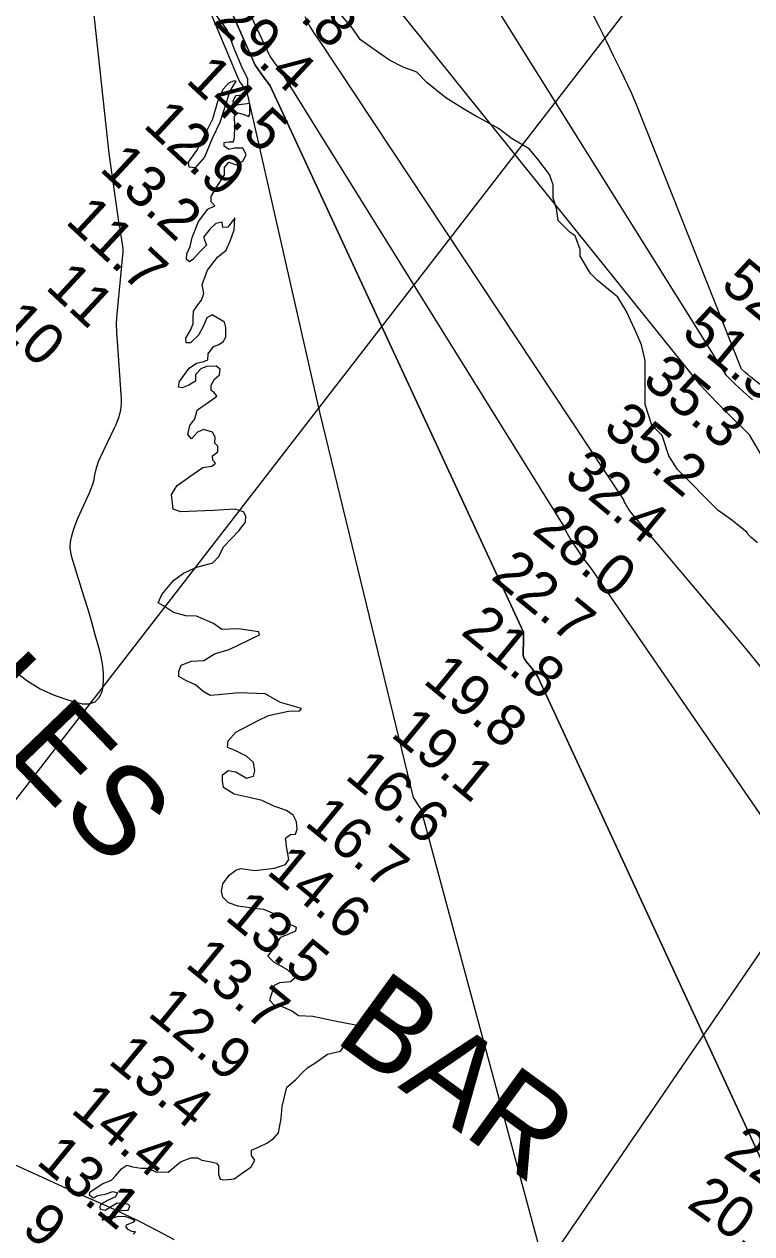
# Model space of a CAD drawing. Extents: x 3161615 to 3199515, y 867541 to 892976.
# Drawn here: x 3182551 to 3183730, y 879343 to 881302 of the extents above; entities that cross this region are included whole.
import ezdxf

# ---------------------------------------------------------------- set-up
doc = ezdxf.new("R2010")
doc.units = 0
for name, color, linetype in [('V-RIVR-EDGE', 7, 'Continuous'), ('V-RIVR-IDEN', 7, 'Continuous'), ('V-RIVR-RANG', 7, 'Continuous'), ('V-SITE-VEGE', 7, 'Continuous'), ('V-TOPO-DPTH', 7, 'Continuous'), ('V-TOPO-MAJR', 7, 'Continuous'), ('V-TOPO-MINR', 7, 'Continuous'), ('V-TOPO-WATR', 7, 'Continuous')]:
    doc.layers.add(name, color=color, linetype=linetype)

msp = doc.modelspace()

# ---------------------------------------------------------------- linework, layer by layer
at = {"layer": 'V-RIVR-EDGE'}
for points in [[(3182813, 880793.6), (3182820.6, 880806.9), (3182824.5, 880816.9), (3182824.5, 880826), (3182825, 880837.4), (3182830.7, 880845.5), (3182838.4, 880855.5), (3182841.8, 880866), (3182839.4, 880880.8), (3182848.1, 880903.6), (3182864.3, 880925), (3182878.2, 880936.5), (3182885.4, 880952.2), (3182891.1, 880968.9), (3182892.1, 880988.4), (3182880.7, 880973.6), (3182873, 880973.2), (3182871.6, 880981.8), (3182861.6, 880979.4), (3182852, 880970.9), (3182841.5, 880957.1), (3182846.3, 880944.2), (3182835.7, 880933.7), (3182824.3, 880921.3), (3182818.5, 880917.1), (3182813.8, 880920.9), (3182814.3, 880930.4), (3182820, 880942.3), (3182822.9, 880956.6), (3182833.5, 880982.8), (3182848.3, 881002.8), (3182859.8, 881008), (3182853.6, 881014.7), (3182854.1, 881023.3), (3182863.2, 881039), (3182875.6, 881058.5), (3182875.7, 881070), (3182882.3, 881078.6), (3182894.3, 881074.7), (3182905.7, 881080.9), (3182910.5, 881091.4), (3182905.3, 881101.4), (3182891.9, 881101.4), (3182882.4, 881099.1), (3182874.8, 881104.8), (3182874.8, 881110.5), (3182882.4, 881111.5), (3182890.1, 881111.9), (3182891.5, 881118.6), (3182892, 881136.7), (3182891.6, 881153.4), (3182897.8, 881158.6), (3182905, 881156.7), (3182915, 881152.9), (3182916.4, 881157.6), (3182916.4, 881173.8), (3182899.3, 881171.5), (3182891.2, 881170.1), (3182889.3, 881177.7), (3182893.6, 881186.8), (3182905, 881187.7), (3182910.3, 881193.4), (3182913.2, 881203.4), (3182913.2, 881213.4), (3182903.2, 881234), (3182891.4, 881263.1), (3182880, 881293.2), (3182862.4, 881316.1)], [(3182893.6, 881209.7), (3182887.9, 881200.1), (3182883.6, 881192.5), (3182878.8, 881176.3), (3182867.7, 881143), (3182855.7, 881117.3), (3182843.3, 881086.8), (3182828, 881069.6), (3182818, 881070.6), (3182817, 881078.7), (3182830.4, 881097.8), (3182846.2, 881128.2), (3182856.3, 881148.7), (3182864.9, 881176.8), (3182873.1, 881196.8)], [(3182873.1, 881196.8), (3182882.7, 881207.3), (3182891.7, 881211.1), (3182893.6, 881209.7)], [(3182928.8, 880173.8), (3182946.9, 880182.3), (3182979.3, 880189.4), (3182997.5, 880190.3), (3183000.3, 880193.7), (3182966, 880203.8), (3182941.3, 880217.7), (3182898.8, 880219.2), (3182865.9, 880215.9), (3182852.1, 880215), (3182840.2, 880222.2), (3182828.3, 880232.2), (3182812.6, 880239.4), (3182801.6, 880245.7), (3182801.6, 880253.8), (3182805, 880264.2), (3182822.2, 880270.4), (3182842.2, 880271.8), (3182859.4, 880282.2), (3182883.3, 880289.3), (3182932, 880313.1), (3182931, 880318.3), (3182897.6, 880323.1), (3182871.4, 880321.8), (3182857.6, 880331.8), (3182830, 880343.3), (3182812.8, 880343.9), (3182792.8, 880349.6), (3182776.6, 880360.2), (3182768, 880365), (3182773.8, 880378.8), (3182792.9, 880401.1), (3182809.2, 880413), (3182830.7, 880423), (3182856.4, 880429.6), (3182866.5, 880440.1), (3182873.7, 880455.8), (3182898.5, 880481.9), (3182909.5, 880495.7), (3182910, 880505.3), (3182906.2, 880512.4), (3182892.4, 880516.8), (3182857.1, 880514.5), (3182804.6, 880512.2), (3182792.3, 880516.5), (3182789.5, 880540.4), (3182799, 880555.2), (3182819.1, 880569.9), (3182840.1, 880584.1), (3182854.9, 880586.5), (3182861.1, 880591.2), (3182856.4, 880596), (3182855.9, 880603.2), (3182864.5, 880609.4), (3182864.5, 880618.9), (3182859.8, 880623.7), (3182860.3, 880633.2), (3182856, 880641.3), (3182841.2, 880645.7), (3182831.7, 880641.4), (3182822.1, 880630.4), (3182815.9, 880637.6), (3182819.3, 880652.4), (3182827.4, 880663.3), (3182831.3, 880677.2), (3182839.4, 880682.9), (3182849, 880689.5), (3182862.8, 880699.5), (3182858.5, 880705.7), (3182853.8, 880709.1), (3182853.8, 880717.6), (3182859.1, 880727.2), (3182867.2, 880734.3), (3182868.2, 880743.3), (3182862, 880748.1), (3182846.2, 880747.7), (3182837.2, 880743.9), (3182828.6, 880734.4), (3182828.5, 880723.9), (3182817.6, 880717.7), (3182806.6, 880713.5), (3182800.9, 880714.4), (3182802.3, 880723.5), (3182818.1, 880744.9), (3182830, 880753), (3182842, 880755.8), (3182848.2, 880758.7), (3182849.2, 880768.2), (3182857.8, 880780.1), (3182865.4, 880782.9), (3182873.5, 880787.7), (3182877.4, 880795.3), (3182877.9, 880811), (3182875.5, 880819.6), (3182855.5, 880831.6), (3182846.9, 880826.9), (3182841.2, 880813.5), (3182833.5, 880798.3), (3182820.1, 880786.4), (3182813.4, 880786.4), (3182813, 880793.6)], [(3182750, 879449.6), (3182764.3, 879443.2), (3182784.4, 879443.1), (3182804.4, 879459.8), (3182821.1, 879466.4), (3182831.6, 879466.4), (3182838.8, 879462.5), (3182854, 879459.6), (3182862.6, 879457.7), (3182865.9, 879453.4), (3182865.9, 879439.6), (3182868.3, 879431.5), (3182874.5, 879430.5), (3182886.4, 879431.4), (3182891.2, 879432.4), (3182918.9, 879451.4), (3182924.6, 879462.3), (3182919.4, 879470), (3182919.4, 879478.5), (3182931.8, 879483.8), (3182945.2, 879490.4), (3182955.2, 879498), (3182962.9, 879506.6), (3182967.2, 879529.9), (3182968.7, 879549.5), (3182976.4, 879580.5), (3182990.7, 879592.3), (3183001.3, 879603.8), (3183010.3, 879612.3), (3183023.7, 879620.4), (3183042.3, 879634.2), (3183063.3, 879638.9), (3183076.7, 879657), (3183092.5, 879664.6), (3183098.7, 879677), (3183087.8, 879680.8), (3183051.5, 879688), (3183018.7, 879694.8), (3182995.3, 879696.3), (3182983.9, 879704), (3182967.7, 879711.1), (3182956.2, 879713.6), (3182949.1, 879720.7), (3182951, 879729.3), (3182956.3, 879746), (3182964.9, 879750.3), (3182982.6, 879751.6), (3182990.7, 879758.8), (3182977.4, 879770.7), (3182965, 879777.9), (3182955.4, 879783.2), (3182945.9, 879792.7), (3182956.5, 879807), (3182967, 879823.7), (3182981.3, 879829.4), (3182990.9, 879833.6), (3182992.3, 879839.4), (3182977.5, 879846.1), (3182970.4, 879856.1), (3182959.9, 879859.9), (3182939, 879868.1), (3182928.5, 879869.6), (3182897.5, 879873.9), (3182882.2, 879879.2), (3182872.7, 879888.3), (3182870.4, 879897.8), (3182872.8, 879909.8), (3182882.8, 879924), (3182893.8, 879932.1), (3182901.9, 879935), (3182924.8, 879931.6), (3182956.3, 879935.3), (3182974.4, 879941), (3182979.7, 879949.1), (3182976.4, 879967.2), (3182974.1, 879983.9), (3182982.7, 879989.6), (3182990.3, 879990.1), (3182993.2, 879998.2), (3182992.3, 880010.6), (3182986.6, 880021.1), (3182976.1, 880028.7), (3182955.6, 880035.5), (3182936.5, 880045), (3182915.6, 880049.9), (3182891.3, 880055.2), (3182874.1, 880066.2), (3182872.2, 880076.7), (3182872.3, 880086.7), (3182881.3, 880093.3), (3182893.7, 880091.4), (3182910.9, 880081.3), (3182922.3, 880084.2), (3182924.7, 880092.8), (3182922.4, 880106.6), (3182911.4, 880116.6), (3182893.8, 880125.3), (3182880.5, 880130.5), (3182881.5, 880141.5), (3182893.9, 880155.3), (3182928.8, 880173.8)], [(3182719.3, 879349.8), (3182715.9, 879353.9), (3182716.4, 879357.7), (3182727.4, 879362), (3182730.3, 879363.9), (3182726, 879367), (3182713.8, 879371), (3182700.7, 879370.6), (3182688.1, 879366.3), (3182677.1, 879365.2), (3182680, 879369), (3182691, 879372.1), (3182694.1, 879377.3), (3182695.5, 879380.2), (3182707.9, 879381.1), (3182719.1, 879381.5), (3182722.2, 879387.7), (3182718.7, 879391.3), (3182701.5, 879392.8), (3182690.5, 879386.4), (3182681.9, 879380.9), (3182674.5, 879382.3), (3182674.1, 879387.4), (3182675.7, 879391.9), (3182686.5, 879397.8), (3182699.4, 879403.7), (3182702, 879409.5), (3182693.7, 879410.9), (3182681.3, 879406.9), (3182669.6, 879404.5), (3182662.4, 879400.7), (3182656.7, 879405.5), (3182657.4, 879410.3), (3182677.3, 879423.8), (3182692.1, 879429.8), (3182699, 879437.1), (3182709, 879448.8), (3182717.1, 879454), (3182726.2, 879451.4), (3182740.5, 879449.4), (3182750, 879449.6)], [(3182727.8, 879342.6), (3182731.4, 879346.2), (3182725.5, 879346.7), (3182719.3, 879349.8)]]:
    msp.add_lwpolyline(points, dxfattribs=at)
at = {"layer": 'V-RIVR-RANG'}
for p, q in [((3181801.2, 879095.8), (3184051.7, 882002.4)), ((3182760.7, 878360.6), (3184853.5, 881422.8))]:
    msp.add_line(p, q, dxfattribs=at)
at = {"layer": 'V-SITE-VEGE'}
for points in [[(3183123.7, 881257.7), (3183096.1, 881277), (3183082.3, 881296.3), (3183038.1, 881348.8)], [(3183739.6, 880462), (3183728.9, 880471.1), (3183726, 880474), (3183724, 880476.4), (3183722.7, 880479), (3183695.1, 880501), (3183675.8, 880514.8), (3183609.6, 880581.1), (3183595.8, 880603.2), (3183584.7, 880636.3), (3183568.2, 880652.9), (3183557.1, 880686), (3183557.1, 880757.8), (3183551.6, 880782.7), (3183540.5, 880807.5), (3183526.7, 880837.9), (3183512.9, 880860), (3183479.8, 880887.6), (3183468.8, 880898.7), (3183452.2, 880926.3), (3183452.2, 880937.3), (3183443.9, 880959.4), (3183435.6, 880964.9), (3183416.3, 880984.3), (3183413.6, 881003.6), (3183408, 881020.2), (3183408, 881042.3), (3183402.5, 881058.8), (3183383.2, 881083.7), (3183369.4, 881100.3), (3183341.8, 881116.8), (3183319.7, 881133.4), (3183289.3, 881150), (3183283.8, 881152.7), (3183264.5, 881163.8), (3183234.1, 881183.1), (3183203.7, 881208), (3183187.2, 881224.5), (3183165.1, 881232.8), (3183143, 881243.9), (3183123.7, 881257.7)]]:
    msp.add_lwpolyline(points, dxfattribs=at)
at = {"layer": 'V-TOPO-DPTH'}
for points in [[(3182637.3, 881885), (3182925.1, 881235.7), (3182937.1, 881219), (3182949.4, 881202.5), (3183360.1, 880317.6), (3183360, 880310.9), (3183359.9, 880304.1), (3183359.9, 880297.4), (3183359.8, 880290.7), (3183359.8, 880280.1), (3183360.2, 880277.4), (3183361.3, 880274.8), (3183362.9, 880272.5), (3183364.6, 880270.2), (3183370, 880263.6), (3183373.5, 880259.1), (3183377, 880254.6), (3183380.3, 880250), (3183383.6, 880245.4), (3183769, 879411.9)], [(3182535.2, 880254.7), (3182555.3, 880239.3), (3182576.6, 880225.9), (3182599.4, 880215.5), (3182623.4, 880207.2), (3182644.6, 880201.5), (3182656.2, 880201.7), (3182666, 880204.8), (3182672.9, 880212.3), (3182677.9, 880222.9), (3182679.3, 880237.4), (3182679.5, 880251.8), (3182677.9, 880266.1), (3182675, 880280.4), (3182671.7, 880292.9), (3182666.1, 880313.3), (3182660.3, 880333.7), (3182654.3, 880354), (3182648.1, 880374.3), (3182628.1, 880439), (3182626.4, 880447), (3182625.5, 880455.1), (3182625.9, 880463.2), (3182627.3, 880471.4), (3182629.6, 880479.5), (3182632.1, 880487.4), (3182635.1, 880495.3), (3182638.4, 880503), (3182656.7, 880543.1), (3182659.6, 880550.1), (3182662.1, 880557.3), (3182664, 880564.7), (3182665.4, 880572.1), (3182666.9, 880579.6), (3182668.9, 880586.9), (3182671.4, 880594), (3182674.4, 880601), (3182697.3, 880648.6), (3182699.7, 880654.1), (3182702, 880659.6), (3182704, 880665.3), (3182705.8, 880671), (3182707.2, 880676.9), (3182708.1, 880682.7), (3182708.4, 880688.7), (3182708.3, 880694.7), (3182701.3, 880796.3), (3182701.1, 880800.1), (3182700.8, 880804), (3182700.7, 880807.9), (3182700.5, 880811.8), (3182700.5, 880815.6), (3182700.6, 880819.5), (3182700.7, 880823.4), (3182701, 880827.3), (3182711.1, 880933.8), (3182711.2, 880936), (3182711.2, 880939.2), (3182710.8, 880942.4), (3182708.4, 880956.8), (3182707, 880965.1), (3182705.7, 880973.4), (3182704.4, 880981.7), (3182703.2, 880990), (3182689, 881089), (3182688.7, 881092.9), (3182604.3, 881870.7)], [(3182535.2, 880254.7), (3182555.3, 880239.3), (3182576.6, 880225.9), (3182599.4, 880215.5), (3182623.4, 880207.2), (3182644.6, 880201.5), (3182656.2, 880201.7), (3182666, 880204.8), (3182672.9, 880212.3), (3182677.9, 880222.9), (3182679.3, 880237.4), (3182679.5, 880251.8), (3182677.9, 880266.1), (3182675, 880280.4), (3182671.7, 880292.9), (3182666.1, 880313.3), (3182660.3, 880333.7), (3182654.3, 880354), (3182648.1, 880374.3), (3182628.1, 880439), (3182626.4, 880447), (3182625.5, 880455.1), (3182625.9, 880463.2), (3182627.3, 880471.4), (3182629.6, 880479.5), (3182632.1, 880487.4), (3182635.1, 880495.3), (3182638.4, 880503), (3182656.7, 880543.1), (3182659.6, 880550.1), (3182662.1, 880557.3), (3182664, 880564.7), (3182665.4, 880572.1), (3182666.9, 880579.6), (3182668.9, 880586.9), (3182671.4, 880594), (3182674.4, 880601), (3182697.3, 880648.6), (3182699.7, 880654.1), (3182702, 880659.6), (3182704, 880665.3), (3182705.8, 880671), (3182707.2, 880676.9), (3182708.1, 880682.7), (3182708.4, 880688.7), (3182708.3, 880694.7), (3182701.3, 880796.3), (3182701.1, 880800.1), (3182700.8, 880804), (3182700.7, 880807.9), (3182700.5, 880811.8), (3182700.5, 880815.6), (3182700.6, 880819.5), (3182700.7, 880823.4), (3182701, 880827.3), (3182711.1, 880933.8), (3182711.2, 880936), (3182711.2, 880939.2), (3182710.8, 880942.4), (3182708.4, 880956.8), (3182707, 880965.1), (3182705.7, 880973.4), (3182704.4, 880981.7), (3182703.2, 880990), (3182689, 881089), (3182688.7, 881092.9), (3182604.3, 881870.7)], [(3182794.3, 879333.4), (3182767.1, 879348), (3182739.7, 879362.1), (3182711.9, 879375.4), (3182683.9, 879388.2), (3182655.3, 879400.7), (3182641.3, 879406.8), (3182627.4, 879413), (3182613.5, 879419.2), (3182599.6, 879425.5), (3182481.4, 879479)], [(3182794.3, 879333.4), (3182767.1, 879348), (3182739.7, 879362.1), (3182711.9, 879375.4), (3182683.9, 879388.2), (3182655.3, 879400.7), (3182641.3, 879406.8), (3182627.4, 879413), (3182613.5, 879419.2), (3182599.6, 879425.5), (3182481.4, 879479)]]:
    msp.add_lwpolyline(points, dxfattribs=at)
at = {"layer": 'V-TOPO-MAJR'}
msp.add_lwpolyline([(3184024.9, 880130.1), (3183726.4, 880637.2), (3183717.2, 880646.3), (3183705.6, 880657.5), (3183690.6, 880672.2), (3183675.8, 880687.1), (3183661.2, 880702.2), (3183646.8, 880717.5), (3183111.1, 881384.2)], dxfattribs=at)
at = {"layer": 'V-TOPO-MINR'}
for points in [[(3183469, 879013.6), (3183197.7, 880018.7), (3183198.1, 880021.4), (3183197.8, 880022.8), (3183196, 880027.2), (3183194.9, 880029.5), (3183193.6, 880031.8), (3183192.2, 880034.1), (3183181.6, 880049.9), (3183030.2, 880674), (3182912.2, 881192.2), (3182899.3, 881211.2), (3182615.6, 881886.6), (3182596.4, 881913.9), (3182577.5, 881941.3), (3182558.6, 881968.9), (3182431.4, 882156.4), (3182416.9, 882180.1), (3182403.8, 882204.5), (3182393, 882229.9), (3182383.6, 882256.1), (3182375, 882284.4), (3182269.1, 882673.7)], [(3183760.2, 879999.8), (3183472.2, 880417.9), (3183467.7, 880423.7), (3183463.3, 880429.5), (3183459.1, 880435.4), (3183454.9, 880441.3), (3183438, 880466), (3183435.7, 880469.5), (3183433.5, 880473.2), (3183431.4, 880476.9), (3183429.5, 880480.7), (3183427.7, 880484.6), (3183426, 880488.5), (3182964, 881230.8), (3182960.3, 881235.4), (3182956.6, 881240.1), (3182953.1, 881244.9), (3182949.6, 881249.7), (3182639.4, 881908.7)], [(3183769, 879411.9), (3183383.6, 880245.4), (3183380.3, 880250), (3183377, 880254.6), (3183373.5, 880259.1), (3183370, 880263.6), (3183364.6, 880270.2), (3183362.9, 880272.5), (3183361.3, 880274.8), (3183360.2, 880277.4), (3183359.8, 880280.1), (3183359.8, 880290.7), (3183359.9, 880297.4), (3183359.9, 880304.1), (3183360, 880310.9), (3183360.1, 880317.6), (3182949.4, 881202.5), (3182937.1, 881219), (3182925.1, 881235.7), (3182637.3, 881885)], [(3183731.1, 880694), (3183716.9, 880706.9), (3183702.8, 880720), (3183689, 880733.3), (3183231.5, 881464.9)], [(3184203.1, 880356.8), (3183728.8, 880730.4), (3183723.6, 880734.7), (3183718.5, 880739), (3183713.4, 880743.5), (3183543.6, 881170.4), (3183535.1, 881191), (3183517.7, 881227.3), (3183506.2, 881251.1), (3183494.5, 881274.8), (3183482.7, 881298.3), (3183470.8, 881321.9)], [(3183746.5, 880259.3), (3183722.6, 880288.5), (3183698.5, 880317.5), (3183674.3, 880346.3), (3183536.3, 880509), (3183534.5, 880511.2), (3183532.8, 880513.4), (3183531.3, 880515.7), (3183529.8, 880518), (3183524.7, 880526.3), (3183523.4, 880528.9), (3183522.5, 880531.6), (3183030.6, 881274.3), (3183021.6, 881287), (3183013.3, 881300.1), (3183006.2, 881313.9)]]:
    msp.add_lwpolyline(points, dxfattribs=at)
at = {"layer": 'V-TOPO-WATR'}
for points in [[(3182535.2, 880254.7), (3182555.3, 880239.3), (3182576.6, 880225.9), (3182599.4, 880215.5), (3182623.4, 880207.2), (3182644.6, 880201.5), (3182656.2, 880201.7), (3182666, 880204.8), (3182672.9, 880212.3), (3182677.9, 880222.9), (3182679.3, 880237.4), (3182679.5, 880251.8), (3182677.9, 880266.1), (3182675, 880280.4), (3182671.7, 880292.9), (3182666.1, 880313.3), (3182660.3, 880333.7), (3182654.3, 880354), (3182648.1, 880374.3), (3182628.1, 880439), (3182626.4, 880447), (3182625.5, 880455.1), (3182625.9, 880463.2), (3182627.3, 880471.4), (3182629.6, 880479.5), (3182632.1, 880487.4), (3182635.1, 880495.3), (3182638.4, 880503), (3182656.7, 880543.1), (3182659.6, 880550.1), (3182662.1, 880557.3), (3182664, 880564.7), (3182665.4, 880572.1), (3182666.9, 880579.6), (3182668.9, 880586.9), (3182671.4, 880594), (3182674.4, 880601), (3182697.3, 880648.6), (3182699.7, 880654.1), (3182702, 880659.6), (3182704, 880665.3), (3182705.8, 880671), (3182707.2, 880676.9), (3182708.1, 880682.7), (3182708.4, 880688.7), (3182708.3, 880694.7), (3182701.3, 880796.3), (3182701.1, 880800.1), (3182700.8, 880804), (3182700.7, 880807.9), (3182700.5, 880811.8), (3182700.5, 880815.6), (3182700.6, 880819.5), (3182700.7, 880823.4), (3182701, 880827.3), (3182711.1, 880933.8), (3182711.2, 880936), (3182711.2, 880939.2), (3182710.8, 880942.4), (3182708.4, 880956.8), (3182707, 880965.1), (3182705.7, 880973.4), (3182704.4, 880981.7), (3182703.2, 880990), (3182689, 881089), (3182688.7, 881092.9), (3182604.3, 881870.7)], [(3182794.3, 879333.4), (3182767.1, 879348), (3182739.7, 879362.1), (3182711.9, 879375.4), (3182683.9, 879388.2), (3182655.3, 879400.7), (3182641.3, 879406.8), (3182627.4, 879413), (3182613.5, 879419.2), (3182599.6, 879425.5), (3182481.4, 879479)]]:
    msp.add_lwpolyline(points, dxfattribs=at)

# ---------------------------------------------------------------- texts
at = {"layer": 'V-RIVR-IDEN'}
for s, rotation, p in [('MILES', 313.9173, (3182292.8, 880352.8)), ('BAR', 323.9173, (3183050.7, 879657))]:
    msp.add_text(s, height=145, rotation=rotation, dxfattribs=at).set_placement(p)
at = {"layer": 'V-RIVR-RANG'}
for s, rotation, p in [('34.8', 316.9183, (3182923.1, 881378.5)), ('29.4', 316.9183, (3182855, 881305.3)), ('14.5', 317.0767, (3182810.9, 881209.3)), ('12.9', 317.0767, (3182741.8, 881137)), ('13.2', 317.0767, (3182671.1, 881066.2)), ('11.7', 317.0767, (3182615.8, 880981.1)), ('11', 317.0767, (3182583.4, 880874.7)), ('52.3', 320.4083, (3183677.5, 880876.3)), ('10', 317.0767, (3182504.4, 880811.5)), ('51.3', 320.4083, (3183614, 880799)), ('35.3', 320.4083, (3183550.5, 880721.8)), ('35.2', 320.4083, (3183486.9, 880644.6)), ('32.4', 320.4083, (3183423.4, 880567.4)), ('28.0', 320.6322, (3183371.9, 880479.7)), ('22.7', 320.6322, (3183305.3, 880405)), ('21.8', 320.6322, (3183256.5, 880315.7)), ('19.8', 320.6322, (3183195.4, 880236.5)), ('19.1', 320.6322, (3183143, 880150)), ('16.6', 320.6322, (3183068.7, 880081.7)), ('16.7', 320.6322, (3183003.1, 880006.1)), ('14.6', 320.6322, (3182941.6, 879927.3)), ('13.5', 320.6322, (3182874, 879853.4)), ('13.7', 320.6322, (3182809.7, 879776.8)), ('12.9', 320.6322, (3182748.8, 879697.4)), ('13.4', 320.6322, (3182684.8, 879620.5)), ('14.4', 320.6322, (3182624.2, 879541)), ('22.9', 324.305, (3183681.6, 879468.5)), ('13.1', 320.6322, (3182568.4, 879457.4)), ('20.2', 324.305, (3183622.8, 879387.6)), ('9', 320.6322, (3182544.4, 879347.7))]:
    msp.add_text(s, height=67, rotation=rotation, dxfattribs=at).set_placement(p)

doc.saveas('drawing.dxf')
